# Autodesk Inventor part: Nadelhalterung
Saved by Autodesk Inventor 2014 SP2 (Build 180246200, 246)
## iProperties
Created: 2015-07
Part Number: Nadelhalterung
Material: Generisch
Document SubType Name: Modeling
Designer: e_krauts
Density: 1 g/cm^3
Appearance: Vorgabe
Mass: 9.06953 g
Surface Area: 36.3222 cm^2
Volume: 9.06953 cm^3
Sending System: SolidWorks 2011
Last Author: e_boekem
Erstellt durch: XYZ
Werkstoff: AlCu4PbMg
Einheit: Stck.
Author: e_krauts
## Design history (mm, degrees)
node "Nadelhalterung.ipt1"
node "Schnitt-Linear austragen2"
node "Basis1"
